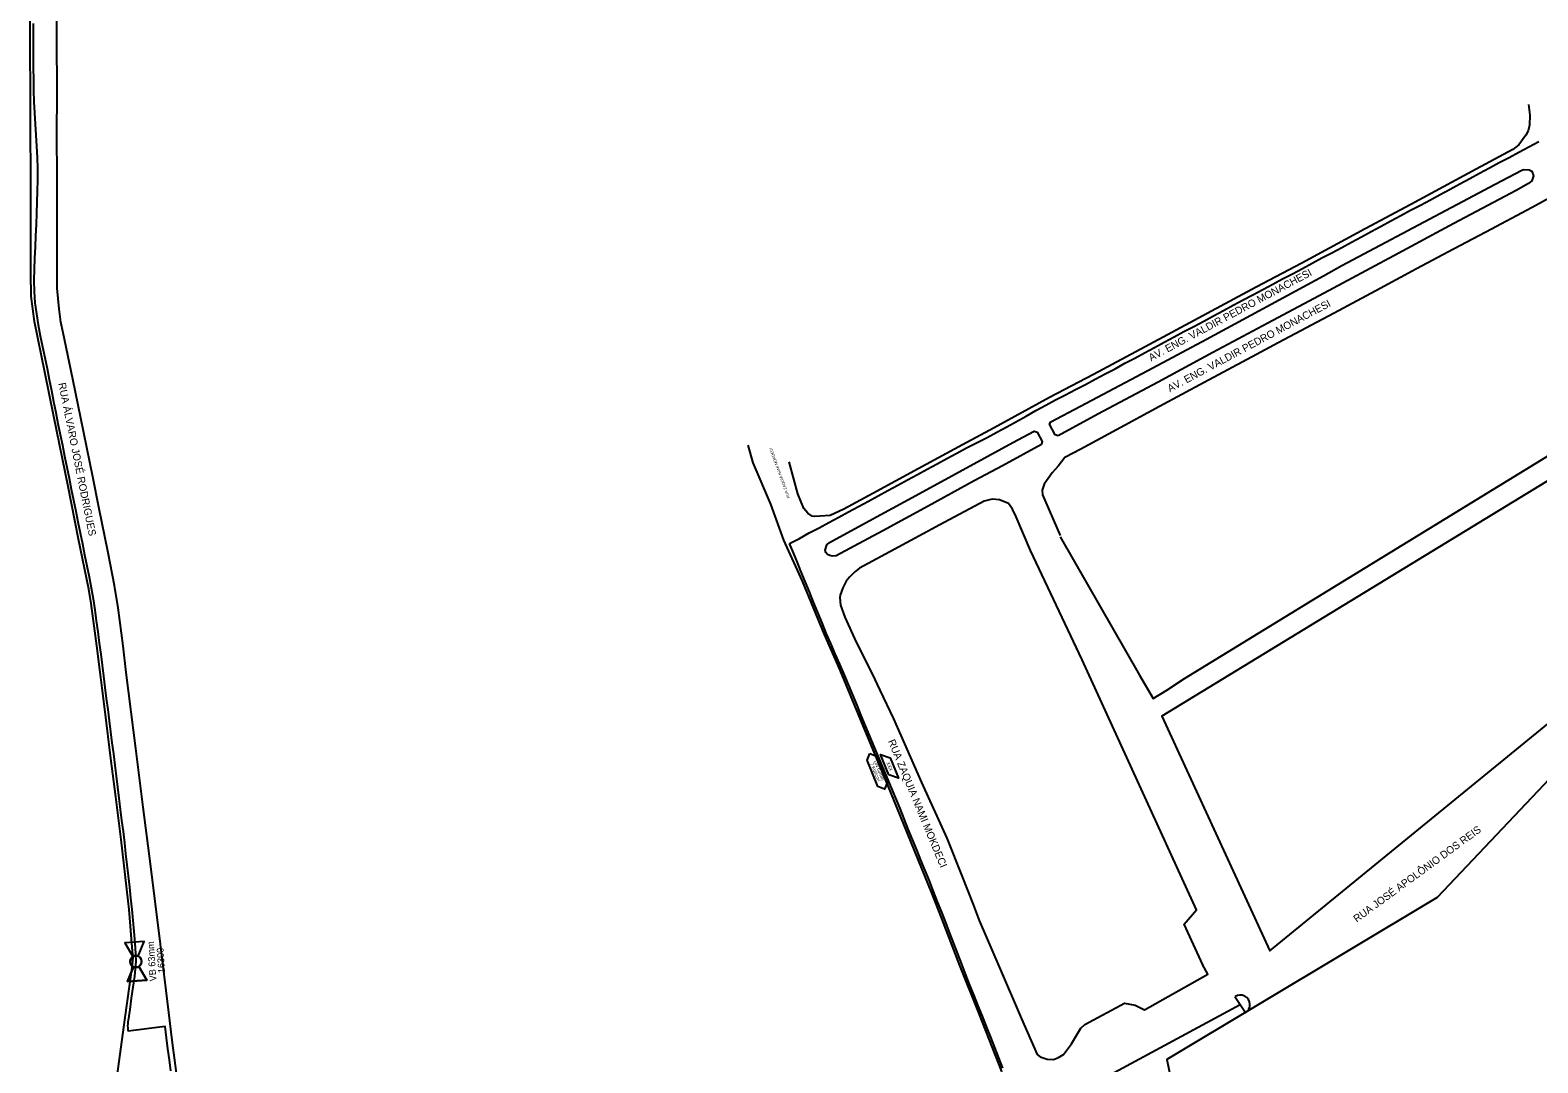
# Model space of a CAD drawing. Extents: x 656692 to 673945, y 7585994 to 7599066.
# Drawn here: x 659366 to 660694, y 7587674 to 7588583 of the extents above; entities that cross this region are included whole.
import ezdxf

# ---------------------------------------------------------------- set-up
doc = ezdxf.new("R2010")
doc.units = 0
for name, color, linetype in [('LOGRADOURO', 7, 'Continuous'), ('LOGRADOURO_TEXTO', 7, 'Continuous'), ('SIMBOLO', 7, 'Continuous'), ('TEXTO', 7, 'Continuous'), ('TUBO_PEAD_GN_63', 7, 'Continuous'), ('VALVULA_PEAD_63', 7, 'Continuous')]:
    doc.layers.add(name, color=color, linetype=linetype)

# ---------------------------------------------------------------- blocks, each defined once
blk = doc.blocks.new('VALVULA_PEAD_DN_9')
at = {"layer": 'VALVULA_PEAD_63'}
for points in [[(-1.14, 0.57), (-4.25, 2.13), (-4.25, -2.13), (-1.14, -0.57)], [(-1.14, -0.57), (-4.25, -2.13), (-4.25, 2.13), (-1.14, 0.57)], [(1.14, -0.57), (4.25, -2.13), (4.25, 2.13), (1.14, 0.57)], [(1.14, -0.57), (4.25, -2.13), (4.25, 2.13), (1.14, 0.57)]]:
    blk.add_lwpolyline(points, dxfattribs=at)
blk.add_circle((0, 0), 1.28, dxfattribs=at)
for start, end in [(90, 270), (153.4349, 206.5651), (270, 90), (0, 26.5651), (333.4349, 0)]:
    blk.add_arc((0, 0), 1.28, start, end, dxfattribs=at)

msp = doc.modelspace()

# ---------------------------------------------------------------- linework, layer by layer
at = {"layer": 'LOGRADOURO'}
msp.add_line((660294.9, 7587707.4), (660329.6, 7587726.3), dxfattribs=at)
for points in [[(659495.9, 7587658.2), (659491.6, 7587691.5), (659486, 7587737.3), (659479.2, 7587792.7), (659471.3, 7587855.7), (659465.7, 7587898.9), (659459.4, 7587950.4), (659450.9, 7588017.5), (659448, 7588040.9), (659443.7, 7588074.3), (659440.5, 7588094), (659435, 7588122.7), (659426.8, 7588163.1), (659421.4, 7588189.8), (659410.8, 7588241.3), (659403.7, 7588275.8), (659395.3, 7588316.5), (659393.3, 7588325.9), (659391.7, 7588337.8), (659390.1, 7588355.9), (659389.9, 7588374.2), (659389.9, 7588407.3), (659389.9, 7588451), (659389.8, 7588493.8), (659389.9, 7588524.8), (659389.6, 7588579.5), (659389.4, 7588617.4)], [(659441, 7587649.1), (659445.4, 7587681.5), (659449.7, 7587711.5), (659456.2, 7587757.8), (659456.8, 7587766.3), (659456.2, 7587775.7), (659453.3, 7587808.8), (659452.4, 7587816.5), (659446.3, 7587870.3), (659441.6, 7587907.9), (659437.4, 7587941.8), (659432.2, 7587982.8), (659424.9, 7588040.9), (659419.9, 7588078.2), (659417.8, 7588090.9), (659408.9, 7588134.9), (659399.6, 7588181.1), (659387, 7588243), (659379.3, 7588281.8), (659370.2, 7588326.6), (659367.1, 7588348.8), (659366.8, 7588369.1), (659366.8, 7588410.6), (659366.8, 7588465.6), (659366.5, 7588484.3), (659366.5, 7588526.3), (659366.3, 7588567.6), (659366.4, 7588595.2)], [(660685.3, 7588517.7), (660686.5, 7588508.3), (660686.3, 7588499.3), (660685, 7588494.4), (660683, 7588490.6), (660677, 7588482.1), (660671.6, 7588477.9), (660639.4, 7588460.6), (660581.7, 7588429.6), (660541.6, 7588408), (660485.8, 7588378), (660445.6, 7588356.7), (660347.9, 7588304.3), (660302.5, 7588280), (660263.7, 7588259.7), (660215, 7588232.9), (660187.1, 7588218), (660148.1, 7588196.7), (660108.3, 7588175.1), (660082.7, 7588161.3), (660070.5, 7588155.8), (660057.1, 7588154.7), (660054.8, 7588155.2), (660050.8, 7588157.8), (660047.3, 7588161.8), (660042.1, 7588174.7), (660034.6, 7588203)], [(660271.2, 7588226), (660271.2, 7588226), (660268.8, 7588226.7), (660263.7, 7588236.2), (660265, 7588238.1), (660301, 7588257.2), (660354.7, 7588285.7), (660401.9, 7588311), (660504.8, 7588366.6), (660521, 7588375.9), (660656, 7588447.5), (660656, 7588447.5), (660656, 7588447.5), (660679.4, 7588459.9), (660681.4, 7588460.5), (660686.1, 7588460.1), (660688.3, 7588458.8), (660689.8, 7588454.9), (660688.2, 7588450.3), (660685.5, 7588448.1), (660674.5, 7588442), (660659.6, 7588434.1), (660619.7, 7588412.8), (660566.9, 7588384.5), (660505.5, 7588351.6), (660460.4, 7588327.4), (660407.4, 7588299.1), (660359.4, 7588273.1), (660306.3, 7588244.9), (660271.2, 7588226)], [(660715.8, 7588441.8), (660688.5, 7588427), (660647.7, 7588405.3), (660619.5, 7588390.2), (660586.8, 7588372.9), (660554.9, 7588355.7), (660514.3, 7588334), (660465, 7588307.7), (660446, 7588297.5), (660400, 7588272.9), (660360.4, 7588251.6), (660329.6, 7588234.9), (660291.2, 7588214.2), (660277.3, 7588206.9), (660271.3, 7588199.2), (660266, 7588193.3), (660258.9, 7588183.2), (660257.3, 7588178), (660257.5, 7588173.9), (660273, 7588138.1)], [(660273.1, 7588136.8), (660342.8, 7588015.2), (660355.1, 7587994.5), (660367, 7588001.9), (660382.6, 7588012.1), (660850.5, 7588298.8)], [(660850.1, 7588276.3), (660362.6, 7587979), (660457.7, 7587772.3), (660777.7, 7588033.7), (660777.7, 7588033.7)], [(660091.7, 7588128.7), (660075.8, 7588120.2), (660072.4, 7588119.8), (660070.3, 7588120.5), (660068.2, 7588121.4), (660066.8, 7588123.2), (660066.3, 7588125.2), (660067.6, 7588129.8), (660069.9, 7588131.8), (660105, 7588151.1), (660146.1, 7588173.3), (660180.9, 7588192.4), (660231.5, 7588220), (660250.2, 7588230.1), (660252.8, 7588229.1), (660257.2, 7588220.9), (660256.7, 7588218.3), (660222.2, 7588199.5), (660197.5, 7588186.1), (660156.9, 7588163.8), (660116.9, 7588142.3), (660091.7, 7588128.7)], [(659998, 7588217.6), (660002.6, 7588202.1), (660018.2, 7588165.8), (660029.6, 7588134), (660045.9, 7588097.9), (660065.2, 7588051), (660079, 7588019.6), (660100.8, 7587967.1), (660116.3, 7587929.6), (660129.1, 7587899), (660160.1, 7587822.5), (660168.5, 7587800.9), (660184.4, 7587759.5), (660201.7, 7587716.3), (660221.4, 7587666.2), (660221.9, 7587663.5), (660221.2, 7587657.5), (660218.4, 7587652), (660216.4, 7587650.2), (660184.3, 7587633.6)], [(660247.1, 7588125), (660234.4, 7588154.5), (660231.1, 7588161.4), (660227.7, 7588166.4), (660219.8, 7588169.5), (660213.1, 7588170.1), (660206.2, 7588168.2), (660167, 7588147.4), (660126.9, 7588125.8), (660096.5, 7588109.4), (660092.2, 7588106.2), (660087.5, 7588101.5), (660084.7, 7588098), (660081.7, 7588092), (660079.5, 7588085.6), (660079.2, 7588083.4), (660079.7, 7588076.8), (660083.4, 7588066.3), (660093.5, 7588044.3), (660107.6, 7588016.4), (660114.4, 7588002), (660126.4, 7587976.6), (660151.1, 7587920.6), (660173.3, 7587871.7), (660186.6, 7587838.5), (660196.6, 7587813.3), (660201.9, 7587799), (660219.3, 7587758.3), (660238.9, 7587712.4), (660252.7, 7587681), (660255.5, 7587678.9), (660261.7, 7587676.9), (660267.3, 7587676.8), (660271.6, 7587678.5), (660276, 7587681), (660283.1, 7587690.6), (660288.5, 7587699.9), (660291.4, 7587704.3), (660294.9, 7587707.4)], [(660398.4, 7587759.8), (660398.8, 7587760), (660382.2, 7587796), (660393.2, 7587808.6), (660292.6, 7588028.7), (660247.1, 7588125)], [(660792.5, 7588017.5), (660604.9, 7587819.3), (660367, 7587676.8), (660371.4, 7587655.7), (660494.3, 7587345.3), (660494.3, 7587345.3)], [(660329.6, 7587726.2), (660329.7, 7587726.3), (660339, 7587724.5), (660347.4, 7587720.5), (660403.1, 7587751.7), (660398.4, 7587760.2), (660398.4, 7587760.2)]]:
    msp.add_lwpolyline(points, dxfattribs=at)
at = {"layer": 'SIMBOLO'}
msp.add_lwpolyline([(660105.6, 7587946.1), (660111.3, 7587943.7), (660120.8, 7587920.3), (660118.4, 7587914.6), (660112.7, 7587917), (660103.2, 7587940.4), (660105.6, 7587946.1)], dxfattribs=at)
msp.add_lwpolyline([(660122.3, 7587927.4), (660115, 7587945.2), (660123.5, 7587942.2), (660130.8, 7587924.4)], close=True, dxfattribs=at)
at = {"layer": 'TUBO_PEAD_GN_63'}
for p, q in [((660436.3, 7587717.8), (660427, 7587732)), ((659452.3, 7587703), (659452.4, 7587701.7))]:
    msp.add_line(p, q, dxfattribs=at)
for points in [[(659369, 7588589), (659369, 7588579.1), (659368.9, 7588569.3), (659369, 7588559.4), (659369, 7588549.6), (659369.1, 7588539.8), (659369.2, 7588529.9), (659369.5, 7588520.1), (659370, 7588510.3), (659370.6, 7588500.4), (659371.2, 7588490.6), (659371.8, 7588480.8), (659372.3, 7588470.9), (659372.7, 7588461.1), (659372.6, 7588451.3), (659372.4, 7588441.4), (659372.1, 7588431.6), (659371.8, 7588421.8), (659371.5, 7588411.9), (659371.1, 7588402.1), (659370.6, 7588392.3), (659370.1, 7588382.4), (659369.7, 7588372.6), (659369.5, 7588362.8), (659369.7, 7588352.9), (659370.4, 7588343.1), (659371.7, 7588333.4), (659373.3, 7588323.6), (659375.2, 7588314), (659377.2, 7588304.3), (659379.1, 7588294.7), (659381.1, 7588285.1), (659383, 7588275.4), (659385, 7588265.7), (659386.9, 7588256.1), (659388.8, 7588246.4), (659390.7, 7588236.8), (659392.7, 7588227.1), (659394.6, 7588217.5), (659396.6, 7588207.9), (659398.6, 7588198.2), (659400.6, 7588188.6), (659402.5, 7588178.9), (659404.5, 7588169.3), (659406.4, 7588159.6), (659408.3, 7588150), (659410.3, 7588140.3), (659412.2, 7588130.7), (659414.2, 7588121), (659416.1, 7588111.4), (659418.1, 7588101.7), (659420, 7588092.1), (659421.7, 7588082.4), (659423.2, 7588072.7), (659424.5, 7588062.9), (659425.8, 7588053.2), (659427.1, 7588043.4), (659428.4, 7588033.6), (659429.6, 7588023.9), (659430.8, 7588014.1), (659432.1, 7588004.3), (659433.3, 7587994.6), (659434.5, 7587984.8), (659435.8, 7587975), (659437, 7587965.3), (659438.2, 7587955.5), (659439.5, 7587945.8), (659440.7, 7587936), (659441.9, 7587926.2), (659443.1, 7587916.4), (659444.3, 7587906.7), (659445.5, 7587896.9), (659446.7, 7587887.1), (659448, 7587877.4), (659449.2, 7587867.6), (659450.3, 7587857.8), (659451.4, 7587848.1), (659452.5, 7587838.3), (659453.6, 7587828.5), (659454.7, 7587818.7), (659455.8, 7587808.9), (659456.7, 7587799.1), (659457.5, 7587789.3), (659458.4, 7587779.5), (659459, 7587769.7), (659459.3, 7587763), (659458, 7587750.1), (659456.6, 7587740.3), (659455.3, 7587730.6), (659453.9, 7587720.8), (659452.5, 7587711.1), (659452.3, 7587709.8)], [(660208.7, 7588224.5), (660217.3, 7588229.1), (660226, 7588233.8), (660234.6, 7588238.6), (660243.2, 7588243.3), (660251.8, 7588248.1), (660260.5, 7588252.8), (660269.1, 7588257.5), (660277.8, 7588262.1), (660286.6, 7588266.6), (660295.3, 7588271.2), (660304, 7588275.8), (660312.7, 7588280.4), (660321.4, 7588285), (660330, 7588289.7), (660338.7, 7588294.3), (660347.4, 7588299), (660356.1, 7588303.6), (660364.7, 7588308.3), (660373.4, 7588312.9), (660382.1, 7588317.6), (660390.8, 7588322.2), (660399.5, 7588326.9), (660408.1, 7588331.5), (660416.8, 7588336.2), (660425.5, 7588340.8), (660434.1, 7588345.5), (660442.8, 7588350.1), (660451.5, 7588354.7), (660460.2, 7588359.4), (660468.9, 7588364), (660477.6, 7588368.6), (660486.3, 7588373.2), (660495, 7588377.8), (660503.6, 7588382.5), (660512.3, 7588387.1), (660521, 7588391.8), (660529.7, 7588396.4), (660538.3, 7588401.1), (660547, 7588405.8), (660555.7, 7588410.4), (660564.3, 7588415.1), (660573, 7588419.8), (660581.6, 7588424.5), (660590.3, 7588429.1), (660599, 7588433.8), (660607.7, 7588438.4), (660616.3, 7588443.1), (660625, 7588447.7), (660633.7, 7588452.4), (660642.4, 7588457.1), (660651, 7588461.7), (660659.7, 7588466.4), (660668.4, 7588471), (660677, 7588475.7), (660685.7, 7588480.4), (660694.4, 7588485)], [(660034.8, 7588131), (660043.5, 7588135.6), (660052.1, 7588140.3), (660060.8, 7588144.9), (660069.5, 7588149.6), (660078.2, 7588154.3), (660086.8, 7588158.9), (660095.5, 7588163.6), (660104.2, 7588168.2), (660112.8, 7588172.9), (660121.5, 7588177.6), (660130.1, 7588182.3), (660138.8, 7588187), (660147.4, 7588191.7), (660156.1, 7588196.4), (660164.7, 7588201.1), (660173.3, 7588205.9), (660182, 7588210.6), (660190.6, 7588215.3), (660208.7, 7588224.5), (660208.7, 7588224.5), (660208.7, 7588224.5)], [(660222.7, 7587669), (660219.1, 7587678.2), (660215.5, 7587687.3), (660211.9, 7587696.5), (660208.3, 7587705.6), (660204.7, 7587714.8), (660201, 7587723.9), (660197.4, 7587733.1), (660193.7, 7587742.2), (660190.1, 7587751.3), (660186.4, 7587760.5), (660182.9, 7587769.7), (660179.4, 7587778.9), (660175.8, 7587788), (660172.3, 7587797.2), (660168.8, 7587806.4), (660165.2, 7587815.6), (660161.6, 7587824.7), (660157.9, 7587833.9), (660154.2, 7587843), (660150.5, 7587852.1), (660146.8, 7587861.2), (660143.1, 7587870.4), (660139.4, 7587879.5), (660135.8, 7587888.6), (660132.1, 7587897.7), (660128.3, 7587906.8), (660124.5, 7587915.9), (660120.7, 7587925), (660116.9, 7587934.1), (660113.1, 7587943.2), (660109.3, 7587952.2), (660105.6, 7587961.3), (660101.8, 7587970.4), (660098, 7587979.5), (660094.3, 7587988.6), (660090.5, 7587997.7), (660086.7, 7588006.8), (660082.9, 7588015.9), (660079.1, 7588024.9), (660075.1, 7588033.9), (660071.1, 7588042.9), (660067.2, 7588052), (660063.5, 7588061.1), (660059.7, 7588070.2), (660056, 7588079.3), (660052.3, 7588088.4), (660048.5, 7588097.5), (660044.8, 7588106.6), (660041.1, 7588115.7), (660037.3, 7588124.8), (660034.8, 7588131)], [(660166.2, 7587619.6), (660180.4, 7587589.6), (660431.6, 7587725), (660431.6, 7587725)], [(659490.1, 7587666.6), (659488.8, 7587676.4), (659487.6, 7587686.1), (659486.3, 7587695.9), (659485.1, 7587705.7), (659452.4, 7587701.7)]]:
    msp.add_lwpolyline(points, dxfattribs=at)
for centre, radius, start, end in [((660431.7, 7587724.9), 8.51, 303.061, 123.061), ((659478.3, 7587706.1), 26.2, 171.9328, 186.95)]:
    msp.add_arc(centre, radius, start, end, dxfattribs=at)

# ---------------------------------------------------------------- block references
at = {"layer": 'VALVULA_PEAD_63', "xscale": 3.999999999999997, "yscale": 3.999999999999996, "rotation": 93.64012251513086}
msp.add_blockref('VALVULA_PEAD_DN_9', (659459.3, 7587763), dxfattribs=at)

# ---------------------------------------------------------------- texts
for s, p in [('VB 63mm', (659477.4, 7587745.7)), ('16300', (659485, 7587753))]:
    msp.add_text(s, height=6, rotation=93.6401).set_placement(p)
at = {"layer": 'LOGRADOURO_TEXTO'}
for s, height, rotation, p in [('AV. ENG. VALDIR PEDRO MONACHESI', 6.562, 28.192, (660353.1, 7588291.3)), ('AV. ENG. VALDIR PEDRO MONACHESI', 6.562, 28.192, (660369.7, 7588264.1)), ('RUA ÁLVARO JOSÉ RODRIGUES', 6.562, 281.3643, (659391, 7588272)), ('RUA ZAQUIA NAMI MOKDECI', 2.461, 109.9292, (660035.2, 7588171.4)), ('RUA ZAQUIA NAMI MOKDECI', 6.562, 292.5343, (660121.3, 7587957)), ('RUA JOSÉ APOLÔNIO DOS REIS', 6.562, 36.1941, (660534.2, 7587797.1))]:
    msp.add_text(s, height=height, rotation=rotation, dxfattribs=at).set_placement(p)
at = {"layer": 'TEXTO'}
for s, p in [('7 Kgf/cm²', (660105.6, 7587937.4)), ('DN 63mm', (660108.9, 7587939.3)), ('XXX', (660119.9, 7587938.1))]:
    msp.add_text(s, height=3, rotation=292.2207, dxfattribs=at).set_placement(p)

doc.saveas('drawing.dxf')
